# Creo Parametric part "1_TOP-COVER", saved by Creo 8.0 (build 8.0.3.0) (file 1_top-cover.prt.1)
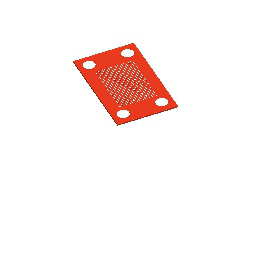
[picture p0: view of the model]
Units: millimeter Newton Second (mmNs); MM, TONNE, SECS

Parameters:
  SMT_DFLT_BEND_REL_LENGTH_TYPE = "Through All"

Other parameters: SMT_PART_BEND_ALLOWANCE_FACTOR, SMT_DFLT_BEND_RADIUS, SMT_DFLT_BEND_ANGLE, SMT_DFLT_CRNR_REL_WIDTH, SMT_DFLT_CRNR_REL_DEPTH, SMT_DFLT_BEND_REL_WIDTH, SMT_DFLT_BEND_REL_DEPTH, SMT_DFLT_BEND_REL_LENGTH, SMT_DFLT_BEND_REL_ANGLE, SMT_GAP, SMT_DFLT_EDGE_TREA_WIDTH, SMT_DFLT_MITER_CUT_WIDTH, SMT_DFLT_MITER_CUT_OFFSET

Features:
  1. datum plane "DTM1"
  2. datum plane "DTM2"
  3. datum plane "DTM3"
  4. datum plane "DTM5"
  5. datum plane "DTM10"
  6. protrusion
  7. round
  8. cut
  9. cut
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
Other named items: COPIED_GROUP, COPIED_GROUP_1, RIGHT, TOP, FRONT, CS0, CS1, CS2

Layers: 0_ALL_AXIS, 0_ALL_CSYS, 0_ALL_CURVES, 0_ALL_PLANES, 0_ALL_POINTS, 0_ALL_SURFS, TOP-COVER

Surfaces: 508 cylinder, 34 plane, 32 torus, 16 cone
